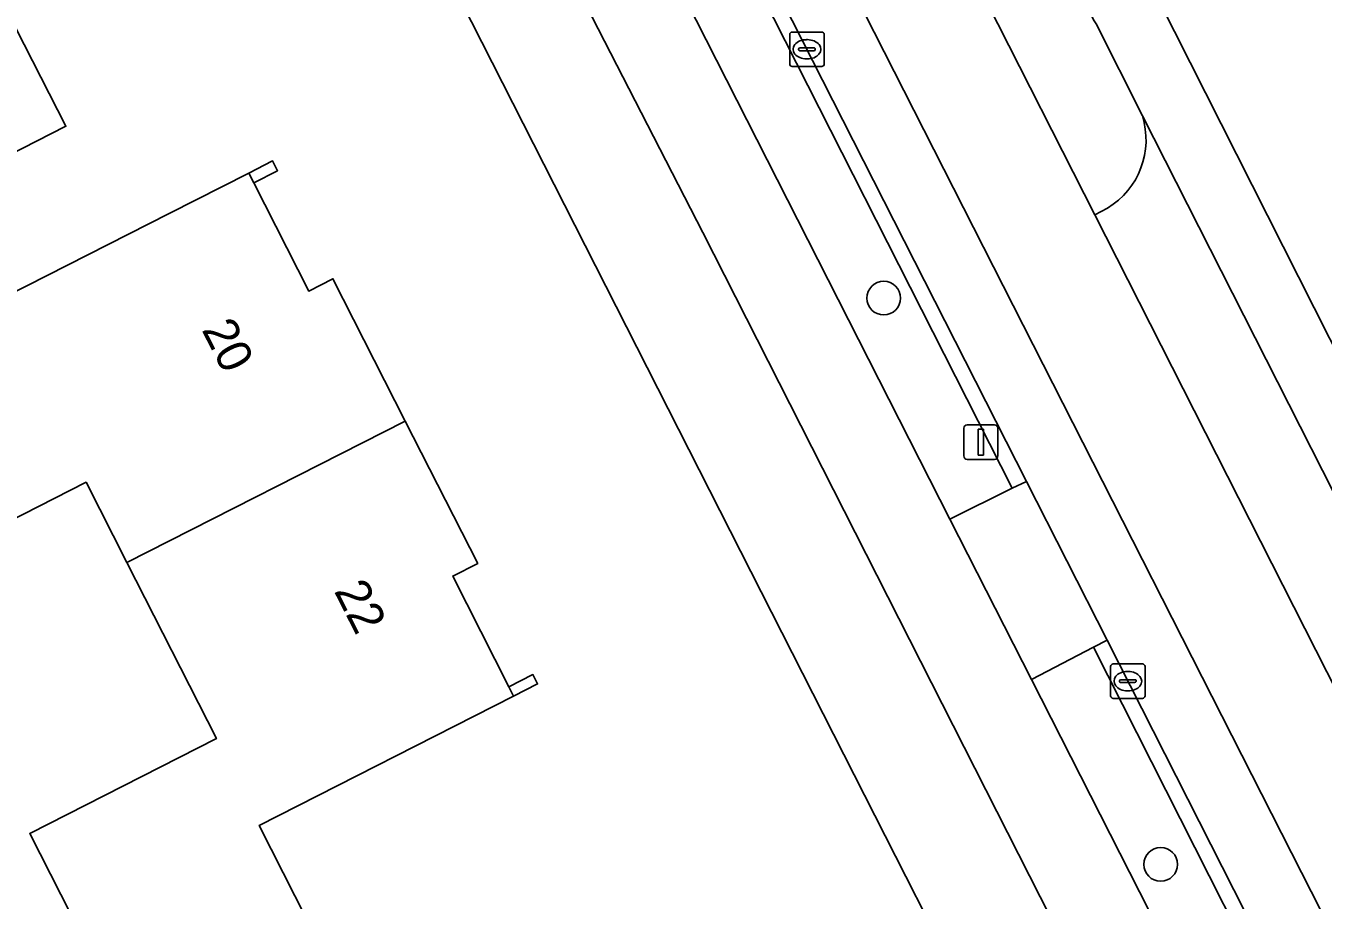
# Model space of a CAD drawing. Extents: x 162417 to 163722, y 384268 to 385417.
# Drawn here: x 163527.82 to 163565.46, y 385007.6 to 385032.96 of the extents above; entities that cross this region are included whole.
import ezdxf

# ---------------------------------------------------------------- set-up
doc = ezdxf.new("R2010")
doc.units = 0
for name, color, linetype in [('IMGEO_Berm_groen', 7, 'Continuous'), ('IMGEO_Boom', 7, 'Continuous'), ('IMGEO_Erf', 7, 'Continuous'), ('IMGEO_Kolk', 7, 'Continuous'), ('IMGEO_Lichtmast', 7, 'Continuous'), ('IMGEO_Muur', 7, 'Continuous'), ('IMGEO_Pand', 7, 'Continuous'), ('IMGEO_Pand_nummerreeks', 7, 'Continuous'), ('IMGEO_Parkeervlak_open', 7, 'Continuous'), ('IMGEO_Rijbaan_lokaal_gesloten', 7, 'Continuous'), ('IMGEO_Verkeerseiland_groen', 7, 'Continuous'), ('IMGEO_Voetpad_open', 7, 'Continuous')]:
    doc.layers.add(name, color=color, linetype=linetype)

msp = doc.modelspace()

# ---------------------------------------------------------------- linework, layer by layer
at = {"layer": 'IMGEO_Berm_groen'}
for points in [[(163547.877, 385036.425), (163546.082, 385035.462), (163554.626, 385018.654), (163556.439, 385019.546)], [(163558.795, 385014.933), (163556.997, 385013.998), (163564.115, 385000), (163565.538, 384997.201), (163567.319, 384998.076), (163566.347, 385000)]]:
    msp.add_lwpolyline(points, close=True, dxfattribs=at)
at = {"layer": 'IMGEO_Boom'}
for centre in [(163552.708, 385025.065), (163560.744, 385008.632)]:
    msp.add_circle(centre, 0.489, dxfattribs=at)
at = {"layer": 'IMGEO_Erf'}
for points in [[(163571.782, 384971.962), (163557.559, 385000), (163534.443, 385045.503), (163500, 385031.078), (163425.859, 385000), (163365.371, 384974.629), (163363.507, 384973.847), (163366.161, 384967.778), (163366.55, 384967.171), (163368.242, 384964.531)], [(163527.526, 385032.903), (163528.977, 385030.051), (163525.618, 385028.342)], [(163527.257, 385025.12), (163531.979, 385027.521), (163534.283, 385028.693), (163534.973, 385029.044), (163535.118, 385028.759), (163534.428, 385028.407), (163536.022, 385025.271), (163536.725, 385025.629), (163538.825, 385021.498), (163540.927, 385017.365), (163540.202, 385016.996), (163541.834, 385013.785), (163542.529, 385014.139), (163542.666, 385013.871), (163541.97, 385013.517), (163534.582, 385009.76), (163536.318, 385006.346)], [(163530.938, 385003.608), (163527.927, 385009.53), (163533.344, 385012.285), (163530.746, 385017.393), (163529.562, 385019.721), (163525.884, 385017.852)]]:
    msp.add_lwpolyline(points, dxfattribs=at)
at = {"layer": 'IMGEO_Kolk'}
for p, q in [((163549.98, 385031.859), (163549.98, 385032.711)), ((163550.055, 385032.785), (163550.907, 385032.785)), ((163550.981, 385032.711), (163550.981, 385031.859)), ((163550.282, 385032.328), (163550.68, 385032.328)), ((163550.468, 385032.565), (163550.493, 385032.565)), ((163550.239, 385032.279), (163550.239, 385032.291)), ((163550.677, 385032.242), (163550.279, 385032.242)), ((163550.491, 385032.005), (163550.466, 385032.005)), ((163550.723, 385032.291), (163550.723, 385032.279)), ((163550.907, 385031.785), (163550.055, 385031.785)), ((163559.29, 385013.523), (163559.29, 385014.375)), ((163559.365, 385014.449), (163560.217, 385014.449)), ((163560.291, 385014.375), (163560.291, 385013.523)), ((163559.549, 385013.943), (163559.549, 385013.955)), ((163559.987, 385013.906), (163559.589, 385013.906)), ((163559.592, 385013.992), (163559.99, 385013.992)), ((163559.778, 385014.229), (163559.803, 385014.229)), ((163560.033, 385013.955), (163560.033, 385013.943)), ((163559.801, 385013.669), (163559.776, 385013.669)), ((163560.217, 385013.449), (163559.365, 385013.449))]:
    msp.add_line(p, q, dxfattribs=at)
for points in [[(163549.98, 385031.859), (163549.98, 385032.711)], [(163550.055, 385032.785), (163550.907, 385032.785)], [(163550.981, 385032.711), (163550.981, 385031.859)], [(163550.907, 385031.785), (163550.055, 385031.785)], [(163559.29, 385013.523), (163559.29, 385014.375)], [(163559.365, 385014.449), (163560.217, 385014.449)], [(163560.291, 385014.375), (163560.291, 385013.523)], [(163560.217, 385013.449), (163559.365, 385013.449)]]:
    msp.add_lwpolyline(points, dxfattribs=at)
for centre, radius, start, end in [((163550.057, 385032.709), 0.0765, 91.552, 178.448), ((163550.057, 385032.709), 0.0765, 91.552, 178.448), ((163550.905, 385032.709), 0.0765, 1.552, 88.448), ((163550.905, 385032.709), 0.0765, 1.552, 88.448), ((163550.279, 385032.288), 0.0403, 85.8775, 175.7526), ((163550.684, 385032.29), 0.0386, 1.7309, 96.639), ((163550.276, 385032.278), 0.0366, 178.938, 274.7102), ((163550.68, 385032.285), 0.043, 264.8664, 352.4533), ((163550.057, 385031.861), 0.0765, 181.552, 268.448), ((163550.057, 385031.861), 0.0765, 181.552, 268.448), ((163550.905, 385031.861), 0.0765, 271.552, 358.448), ((163550.905, 385031.861), 0.0765, 271.552, 358.448), ((163559.367, 385014.373), 0.0765, 91.552, 178.448), ((163559.367, 385014.373), 0.0765, 91.552, 178.448), ((163560.215, 385014.373), 0.0765, 1.552, 88.448), ((163560.215, 385014.373), 0.0765, 1.552, 88.448), ((163559.589, 385013.952), 0.0403, 85.8775, 175.7526), ((163559.586, 385013.942), 0.0366, 178.938, 274.7102), ((163559.99, 385013.949), 0.043, 264.8664, 352.4533), ((163559.994, 385013.954), 0.0386, 1.7309, 96.639), ((163559.367, 385013.525), 0.0765, 181.552, 268.448), ((163559.367, 385013.525), 0.0765, 181.552, 268.448), ((163560.215, 385013.525), 0.0765, 271.552, 358.448), ((163560.215, 385013.525), 0.0765, 271.552, 358.448)]:
    msp.add_arc(centre, radius, start, end, dxfattribs=at)
for centre, major_axis, ratio, start_param, end_param in [((163550.467, 385032.285), (-0.387, 0.002), 0.722429, 4.712389, 7.853982), ((163550.492, 385032.285), (-0.39, 0.002), 0.717154, 1.570796, 4.712389), ((163559.777, 385013.949), (-0.387, 0.002), 0.722429, 4.712389, 7.853982), ((163559.802, 385013.949), (-0.39, 0.002), 0.717154, 1.570796, 4.712389)]:
    msp.add_ellipse(centre, major_axis=major_axis, ratio=ratio, start_param=start_param, end_param=end_param, dxfattribs=at)
at = {"layer": 'IMGEO_Lichtmast'}
for p, q in [((163555.029, 385020.486), (163555.029, 385021.286)), ((163555.029, 385021.286), (163555.029, 385020.486)), ((163555.129, 385021.386), (163555.919, 385021.386)), ((163555.919, 385021.386), (163555.129, 385021.386)), ((163556.019, 385021.286), (163556.019, 385020.486)), ((163556.019, 385020.486), (163556.019, 385021.286)), ((163555.919, 385020.386), (163555.129, 385020.386)), ((163555.129, 385020.386), (163555.919, 385020.386))]:
    msp.add_line(p, q, dxfattribs=at)
msp.add_lwpolyline([(163555.449, 385021.261), (163555.599, 385021.261), (163555.599, 385020.511), (163555.449, 385020.511), (163555.449, 385021.261)], dxfattribs=at)
for centre, start, end in [((163555.129, 385021.286), 90, 180), ((163555.129, 385021.286), 90, 180), ((163555.919, 385021.286), 0, 90), ((163555.919, 385021.286), 360, 90), ((163555.129, 385020.486), 180, 270), ((163555.129, 385020.486), 180, 270), ((163555.919, 385020.486), 270, 0), ((163555.919, 385020.486), 270, 0)]:
    msp.add_arc(centre, 0.1, start, end, dxfattribs=at)
at = {"layer": 'IMGEO_Muur'}
for points in [[(163534.283, 385028.693), (163534.428, 385028.407), (163535.118, 385028.759), (163534.973, 385029.044)], [(163541.834, 385013.785), (163541.97, 385013.517), (163542.666, 385013.871), (163542.529, 385014.139)]]:
    msp.add_lwpolyline(points, close=True, dxfattribs=at)
at = {"layer": 'IMGEO_Pand'}
for points in [[(163536.725, 385025.629), (163536.022, 385025.271), (163534.428, 385028.407), (163534.283, 385028.693), (163531.979, 385027.521), (163527.257, 385025.12), (163525.618, 385028.342), (163528.977, 385030.051), (163527.526, 385032.903), (163516.318, 385028.552), (163518.235, 385024.782), (163518.308, 385024.639), (163519.579, 385025.285), (163521.259, 385021.981), (163521.134, 385021.917), (163522.498, 385019.234), (163524.63, 385020.318), (163525.884, 385017.852), (163529.562, 385019.721), (163530.746, 385017.393), (163538.825, 385021.498)], [(163530.746, 385017.393), (163533.344, 385012.285), (163527.927, 385009.53), (163530.938, 385003.608), (163536.318, 385006.346), (163534.582, 385009.76), (163541.97, 385013.517), (163541.834, 385013.785), (163540.202, 385016.996), (163540.927, 385017.365), (163538.825, 385021.498)]]:
    msp.add_lwpolyline(points, close=True, dxfattribs=at)
at = {"layer": 'IMGEO_Parkeervlak_open'}
for points in [[(163575.432, 384986.926), (163570.744, 384996.761), (163569.085, 385000), (163565.691, 385006.707), (163543.493, 385050.372)], [(163543.294, 385046.432), (163546.539, 385040.046), (163548.271, 385036.636), (163556.848, 385019.747), (163559.189, 385015.138), (163566.866, 385000), (163567.737, 384998.282), (163570.733, 384992.372), (163572.639, 384988.612), (163573.286, 384988.089), (163574.262, 384987.926)]]:
    msp.add_lwpolyline(points, dxfattribs=at)
at = {"layer": 'IMGEO_Rijbaan_lokaal_gesloten'}
for points in [[(163587.703, 384981.381), (163574.647, 385006.089), (163556.651, 385041.714), (163548.01, 385057.354), (163546.571, 385054.29)], [(163550.507, 385049.403), (163558.815, 385033.116), (163558.874, 385033.023), (163560.212, 385030.353), (163570.018, 385011.049), (163571.382, 385008.358), (163575.686, 385000), (163581.634, 384988.446), (163581.685, 384988.346), (163582.618, 384986.586), (163586.033, 384980.524), (163587.703, 384981.381)]]:
    msp.add_lwpolyline(points, dxfattribs=at)
msp.add_lwpolyline([(163572.767, 385000), (163569.995, 385005.495), (163566.848, 385011.682), (163558.831, 385027.486), (163555.713, 385033.636), (163549.154, 385046.537), (163545.346, 385054.029), (163543.493, 385050.372), (163565.691, 385006.707), (163569.085, 385000), (163570.744, 384996.761), (163575.432, 384986.926), (163576.284, 384985.149), (163579.304, 384978.533), (163579.742, 384977.454), (163582.97, 384978.933), (163581.337, 384982.561), (163578.372, 384988.883)], close=True, dxfattribs=at)
at = {"layer": 'IMGEO_Verkeerseiland_groen'}
for points in [[(163556.09, 385033.858), (163555.713, 385033.636), (163558.831, 385027.486), (163559.204, 385027.678)], [(163560.212, 385030.353), (163558.874, 385033.023)]]:
    msp.add_lwpolyline(points, dxfattribs=at)
msp.add_arc((163558.004, 385029.658), 2.315, 301.2302, 17.4747, dxfattribs=at)
at = {"layer": 'IMGEO_Voetpad_open'}
for points in [[(163531.103, 385052.107), (163533.125, 385048.062), (163534.443, 385045.503), (163557.559, 385000), (163571.782, 384971.962), (163572.96, 384969.64), (163599.332, 384917.655), (163619.201, 384879.411), (163644.977, 384828.162), (163646.209, 384825.591), (163647.107, 384826.065), (163654.204, 384812.214), (163656.997, 384806.824), (163660.571, 384799.786), (163661.604, 384797.609), (163662.207, 384797.874), (163664.204, 384793.9), (163665.062, 384792.193), (163665.979, 384790.369)], [(163533.893, 385050.706), (163534.186, 385050.269), (163540.137, 385041.23), (163547.457, 385026.967), (163574.621, 384973.481), (163576.974, 384974.74), (163568.539, 384991.295)], [(163653.17, 384818.952), (163649.142, 384826.839), (163632.793, 384858.931), (163623.647, 384877.065), (163596.886, 384929.577), (163577.374, 384968.061), (163574.621, 384973.481), (163547.457, 385026.967), (163540.137, 385041.23), (163534.186, 385050.269), (163533.893, 385050.706)], [(163568.539, 384991.295), (163565.538, 384997.201), (163564.115, 385000), (163556.997, 385013.998), (163554.626, 385018.654), (163546.082, 385035.462), (163544.329, 385038.909), (163543.44, 385040.738)], [(163570.018, 385011.049), (163560.212, 385030.353)], [(163559.204, 385027.678), (163558.831, 385027.486), (163566.848, 385011.682), (163567.255, 385011.87)]]:
    msp.add_lwpolyline(points, dxfattribs=at)
for points in [[(163548.271, 385036.636), (163547.877, 385036.425), (163556.439, 385019.546), (163556.848, 385019.747)], [(163556.439, 385019.546), (163554.626, 385018.654), (163556.997, 385013.998), (163558.795, 385014.933), (163559.189, 385015.138), (163556.848, 385019.747)], [(163558.795, 385014.933), (163566.347, 385000), (163567.319, 384998.076), (163567.737, 384998.282), (163566.866, 385000), (163559.189, 385015.138)]]:
    msp.add_lwpolyline(points, close=True, dxfattribs=at)
msp.add_arc((163558.004, 385029.658), 2.315, 301.2302, 17.4747, dxfattribs=at)

# ---------------------------------------------------------------- texts
at = {"layer": 'IMGEO_Pand_nummerreeks'}
for s, p in [('20', (163532.907, 385024.151)), ('22', (163536.747, 385016.569))]:
    msp.add_text(s, height=1, rotation=296.8658, dxfattribs=at).set_placement(p)

doc.saveas('drawing.dxf')
